// Mitsubishi GX Works2 project: （模拟量）三菱2DA模块模拟量写入台达变频器   PLC: FX3U/FX3UC

PROGRAM MAIN
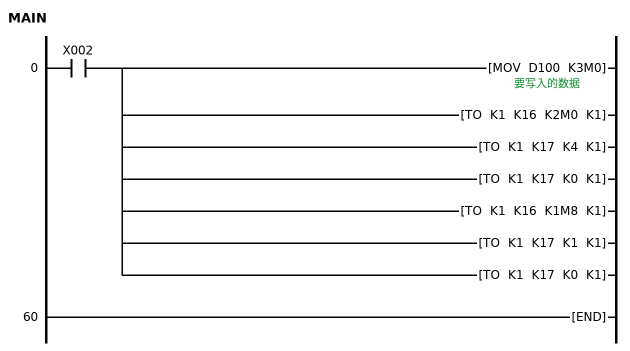
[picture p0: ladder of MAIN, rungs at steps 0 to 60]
0     LD      X002
      MOV     D100 K3M0  ; 要写入的数据 / 写入数据的低8位
        [note] 把要写入的12位数据传到K3M0
      TO      K1 K16 K2M0 K1
        [note] 把低8位存到2#D\A模块的16号D
      TO      K1 K17 K4 K1
        [note] 把17号D的第三位数据先置1
      TO      K1 K17 K0 K1
        [note] 再置0，通过下降沿保持低8位数据
      TO      K1 K16 K1M8 K1  ; 写入数据的高4位
      TO      K1 K17 K1 K1
        [note] 把17号D的第1位数据先置1
      TO      K1 K17 K0 K1
        [note] 再置0，通过下降沿选择通道2
60    END
END_PROGRAM
